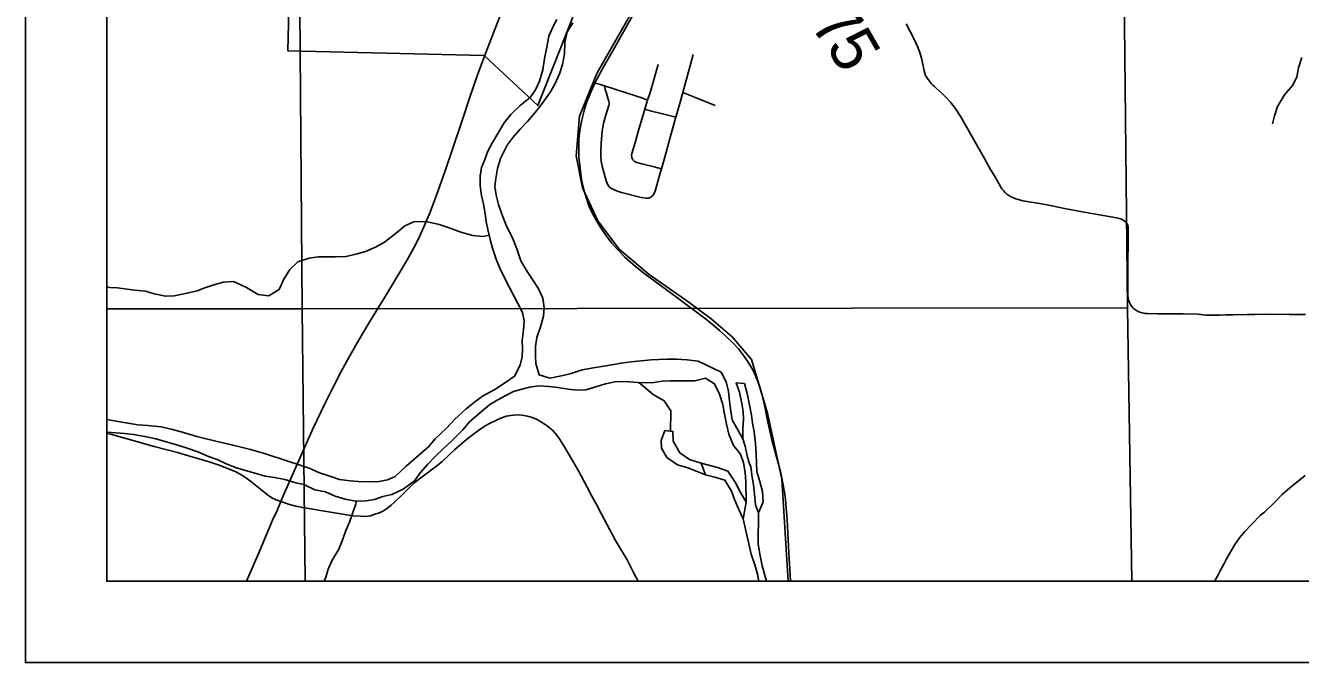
# Model space of a CAD drawing. Extents: x 0 to 34, y 0 to 22.
# Drawn here: x 1.76 to 3.328, y 14.287 to 15.071 of the extents above; entities that cross this region are included whole.
import ezdxf

# ---------------------------------------------------------------- set-up
doc = ezdxf.new("R2010")
doc.units = 0
for name, color, linetype in [('GM_X_County_Road', 7, 'Continuous'), ('GM_X_County_Road_Text', 7, 'Continuous'), ('GM_X_County_Text', 7, 'Continuous'), ('GM_X_Interchange_Ramps', 7, 'Continuous'), ('GM_X_State_Route', 7, 'Continuous'), ('GM_X_State_Shield', 7, 'Continuous'), ('GM_X_Township_Road', 7, 'Continuous'), ('GM_X_Township_Text', 7, 'Continuous'), ('SH_Data', 7, 'Continuous')]:
    doc.layers.add(name, color=color, linetype=linetype)

msp = doc.modelspace()

# ---------------------------------------------------------------- linework, layer by layer
at = {"layer": 'GM_X_County_Road'}
for points in [[(2.3247, 15.0329), (2.3399, 15.072), (2.3515, 15.1008), (2.3595, 15.1196), (2.3705, 15.1452), (2.3805, 15.168)], [(2.2971, 14.9535), (2.3072, 14.9837), (2.3156, 15.0085), (2.3222, 15.0263), (2.3247, 15.0329)], [(2.0742, 14.4847), (2.0773, 14.4916), (2.1142, 14.575), (2.1275, 14.6031), (2.1385, 14.6255), (2.1485, 14.6449), (2.1575, 14.6613), (2.1683, 14.6802), (2.1826, 14.7043), (2.1961, 14.7265), (2.1988, 14.7309), (2.2008, 14.7342), (2.2293, 14.7815), (2.2354, 14.7923), (2.2412, 14.8032), (2.2453, 14.8116), (2.2503, 14.8229), (2.258, 14.8409), (2.266, 14.8629), (2.2758, 14.8905), (2.2857, 14.9196), (2.2971, 14.9535)], [(1.8602, 14.5684), (1.8646, 14.5675), (1.8883, 14.5612), (1.9185, 14.5526), (1.9471, 14.5449), (1.9606, 14.541)], [(1.9606, 14.541), (1.9722, 14.5376), (1.9862, 14.5334), (1.9986, 14.5294), (2.0098, 14.5251), (2.0188, 14.5211), (2.0242, 14.5182), (2.0294, 14.515), (2.0369, 14.5096), (2.0492, 14.5001), (2.0579, 14.4929), (2.0632, 14.4893), (2.0685, 14.4869), (2.0742, 14.4847)], [(2.0321, 14.3866), (2.0485, 14.4246), (2.0642, 14.4618), (2.0696, 14.4738), (2.0742, 14.4847)]]:
    msp.add_lwpolyline(points, dxfattribs=at)
at = {"layer": 'GM_X_County_Road_Text'}
for points in [[(3.3297, 15.0312), (3.3257, 15.0182), (3.3239, 15.0072), (3.319, 14.9969), (3.3085, 14.985), (3.2999, 14.9709), (3.2962, 14.9595), (3.294, 14.9496)], [(2.3306, 14.8123), (2.3231, 14.811), (2.3102, 14.8121), (2.2958, 14.8163), (2.2814, 14.8216), (2.2689, 14.8257), (2.2526, 14.8295), (2.2378, 14.8287), (2.2268, 14.8238), (2.2166, 14.8154), (2.2018, 14.804), (2.1905, 14.7976), (2.1783, 14.7922), (2.1681, 14.7896), (2.1545, 14.7861), (2.1412, 14.7857), (2.1207, 14.7857), (2.109, 14.7842), (2.095, 14.7796), (2.0855, 14.7701), (2.0779, 14.7584), (2.0722, 14.7458), (2.0597, 14.7379), (2.0465, 14.7394), (2.0321, 14.7481), (2.0161, 14.7556), (2.0036, 14.7545), (1.9919, 14.7514), (1.9809, 14.7476), (1.9714, 14.7438), (1.957, 14.7407), (1.943, 14.7377), (1.9324, 14.7373), (1.9183, 14.7403), (1.9077, 14.7437), (1.8948, 14.7448), (1.8854, 14.746), (1.8732, 14.7475), (1.8638, 14.7482), (1.8602, 14.7488)], [(2.5144, 14.6312), (2.5189, 14.6274), (2.5322, 14.6164), (2.5455, 14.6085), (2.5538, 14.5964), (2.5534, 14.5713)], [(2.591, 14.532), (2.577, 14.5365), (2.5649, 14.5448), (2.5569, 14.5589), (2.5565, 14.571), (2.5463, 14.5721), (2.5421, 14.56), (2.5425, 14.5505), (2.549, 14.5391), (2.5619, 14.5297), (2.5747, 14.5263), (2.5861, 14.5217), (2.5967, 14.5176)], [(2.1673, 14.4852), (2.1665, 14.4817), (2.162, 14.4688), (2.1586, 14.4593), (2.1541, 14.4491), (2.1503, 14.4385), (2.1457, 14.4263), (2.1374, 14.4127), (2.1325, 14.4017), (2.1295, 14.3918), (2.1274, 14.3866)]]:
    msp.add_lwpolyline(points, dxfattribs=at)
at = {"layer": 'GM_X_County_Text'}
msp.add_lwpolyline([(2.5564, 15.1755), (2.4633, 15.0123), (2.4414, 14.9588), (2.4376, 14.91), (2.4453, 14.8709), (2.4642, 14.8303), (2.4905, 14.7953), (2.5272, 14.7641), (2.5746, 14.7309), (2.6035, 14.7095), (2.6294, 14.6873), (2.6532, 14.6593), (2.6729, 14.5935), (2.6905, 14.5124), (2.6983, 14.3866)], dxfattribs=at)
at = {"layer": 'GM_X_Interchange_Ramps'}
msp.add_line((2.5219, 14.9677), (2.5253, 14.9785), dxfattribs=at)
for points in [[(2.8432, 15.0726), (2.8531, 15.0536), (2.8572, 15.0448), (2.86, 15.0374), (2.862, 15.0302), (2.864, 15.0209), (2.8654, 15.0149), (2.8663, 15.0117), (2.8672, 15.0091), (2.8687, 15.0065), (2.8705, 15.0041), (2.8722, 15.0015), (2.8741, 14.9992), (2.8761, 14.9972), (2.8781, 14.9954), (2.8803, 14.9935), (2.8871, 14.9873), (2.8915, 14.9828), (2.8979, 14.976), (2.9036, 14.9688), (2.9104, 14.9582), (2.9229, 14.9365), (2.938, 14.9095), (2.9472, 14.8933), (2.9518, 14.8854), (2.9594, 14.8722), (2.961, 14.8697), (2.9629, 14.8673), (2.9649, 14.865), (2.9672, 14.863), (2.9697, 14.8612), (2.9725, 14.8596), (2.9781, 14.8572), (2.9868, 14.8549), (3.0025, 14.8522), (3.0165, 14.8497), (3.038, 14.8452), (3.0622, 14.8408), (3.081, 14.8375), (3.102, 14.8337), (3.1052, 14.8329), (3.108, 14.832), (3.1108, 14.8307), (3.1135, 14.8283), (3.1154, 14.8255), (3.1162, 14.8228), (3.1164, 14.8195), (3.1165, 14.8132), (3.1162, 14.8007), (3.1161, 14.7821), (3.1161, 14.7634), (3.1159, 14.7448), (3.1161, 14.7386), (3.1164, 14.7355), (3.1169, 14.7325), (3.1178, 14.7297), (3.1191, 14.727), (3.1209, 14.7246), (3.123, 14.7224), (3.1253, 14.7205), (3.1279, 14.719), (3.1307, 14.7177), (3.1336, 14.7168), (3.137, 14.7162), (3.1402, 14.716), (3.153, 14.7157), (3.1839, 14.7156), (3.2022, 14.7151), (3.212, 14.7142), (3.2213, 14.7142), (3.2295, 14.7142), (3.2365, 14.7145), (3.2456, 14.7146), (3.2627, 14.7147), (3.2722, 14.715), (3.2915, 14.7151), (3.3148, 14.7149), (3.3344, 14.7149)], [(2.5253, 14.9785), (2.5287, 14.9892), (2.5383, 15.0223)], [(2.5814, 15.0347), (2.5798, 15.0287), (2.5707, 14.9956), (2.5687, 14.9882)], [(2.4606, 14.9996), (2.4659, 14.9981), (2.4724, 14.9961)], [(2.5422, 14.8943), (2.5412, 14.8906), (2.538, 14.8786), (2.5346, 14.8666), (2.5334, 14.8637), (2.5318, 14.8611), (2.5294, 14.8591), (2.5265, 14.858), (2.5235, 14.8579), (2.5174, 14.859), (2.4932, 14.865), (2.4872, 14.8669), (2.4844, 14.8681), (2.4816, 14.8695), (2.479, 14.8712), (2.4769, 14.8735), (2.4755, 14.8763), (2.4745, 14.8792), (2.4696, 14.8973), (2.4684, 14.9034), (2.4678, 14.9096), (2.4677, 14.9158), (2.4683, 14.9252), (2.4696, 14.9407), (2.4711, 14.9499), (2.4734, 14.959), (2.4774, 14.9708), (2.4778, 14.9721), (2.478, 14.9738), (2.4779, 14.9754), (2.4777, 14.9769), (2.4768, 14.9799), (2.4755, 14.9841), (2.4743, 14.9883), (2.4733, 14.9918), (2.4724, 14.9961)], [(2.4724, 14.9961), (2.5103, 14.9839), (2.5184, 14.9815), (2.5211, 14.9803), (2.5253, 14.9785)], [(2.5687, 14.9882), (2.5648, 14.9746), (2.5601, 14.9578)], [(2.5687, 14.9882), (2.5872, 14.9807), (2.6085, 14.972)], [(2.5422, 14.8943), (2.5363, 14.8958), (2.5333, 14.8965), (2.5181, 14.9001), (2.5121, 14.9018), (2.5093, 14.9032), (2.507, 14.9053), (2.5058, 14.9081), (2.5057, 14.9112), (2.5064, 14.9143), (2.511, 14.9292), (2.5142, 14.9413), (2.5193, 14.9594), (2.5219, 14.9677)], [(2.5219, 14.9677), (2.5271, 14.9661), (2.53, 14.9652), (2.5418, 14.9622), (2.5536, 14.9593), (2.5601, 14.9578)], [(2.5601, 14.9578), (2.5597, 14.9566), (2.5546, 14.9387), (2.5455, 14.9056), (2.5422, 14.8943)], [(2.5136, 14.3866), (2.5082, 14.3966), (2.5001, 14.4129), (2.4859, 14.4369), (2.468, 14.4699), (2.4626, 14.4809), (2.4568, 14.4914), (2.4508, 14.5024), (2.4406, 14.5216), (2.4331, 14.5353), (2.4222, 14.5532), (2.4172, 14.5612), (2.4135, 14.5665), (2.4083, 14.5724), (2.4042, 14.5758), (2.4019, 14.5778), (2.3994, 14.5796), (2.3941, 14.583), (2.3887, 14.5861), (2.3835, 14.5881), (2.3776, 14.5896), (2.3706, 14.5909), (2.3638, 14.5913), (2.3571, 14.5906), (2.3512, 14.5896), (2.3448, 14.5875), (2.3394, 14.5849), (2.3315, 14.5813), (2.3254, 14.578), (2.3178, 14.5726), (2.3111, 14.5675), (2.3024, 14.561), (2.2884, 14.5489), (2.2725, 14.5339), (2.2677, 14.5299), (2.2479, 14.515), (2.2379, 14.5072), (2.2314, 14.5007), (2.2242, 14.4938)], [(3.2223, 14.3866), (3.2227, 14.3872), (3.2269, 14.3945), (3.2296, 14.3993), (3.2318, 14.4038), (3.2342, 14.4086), (3.2372, 14.4141), (3.2413, 14.4213), (3.2473, 14.4317), (3.2531, 14.4401), (3.2597, 14.4479), (3.2679, 14.4563), (3.2792, 14.4678), (3.2839, 14.4718), (3.295, 14.4824), (3.3059, 14.4933), (3.3151, 14.5014), (3.3339, 14.5169)], [(2.2242, 14.4938), (2.2141, 14.484), (2.2098, 14.4801), (2.2042, 14.4759), (2.2016, 14.4742), (2.199, 14.4726), (2.1943, 14.4706), (2.1912, 14.4694), (2.1879, 14.4682), (2.1847, 14.4673), (2.1818, 14.4668), (2.1783, 14.4665), (2.1722, 14.4666), (2.1629, 14.4673), (2.1353, 14.4718), (2.1013, 14.4773), (2.0928, 14.479), (2.0851, 14.4811), (2.0742, 14.4847)]]:
    msp.add_lwpolyline(points, dxfattribs=at)
at = {"layer": 'GM_X_State_Route'}
for points in [[(4.1201, 16.507), (4.1149, 16.7255), (3.8667, 16.7261), (3.8624, 16.726), (3.8538, 16.7259), (3.7775, 16.7251), (3.6944, 16.7259), (3.6091, 16.7254), (3.5492, 16.7252), (3.5064, 16.7242), (3.4642, 16.7247), (3.3781, 16.7258), (3.3363, 16.7271), (3.2929, 16.7282), (3.2508, 16.7281), (3.0563, 16.7255), (2.994, 16.7266), (1.8602, 16.7212), (1.8602, 14.3866), (4.1451, 14.3866)], [(2.087, 15.2089), (2.0829, 15.0394), (2.3245, 15.0335), (2.3902, 14.972), (2.4333, 15.0808)]]:
    msp.add_lwpolyline(points, dxfattribs=at)
for points in [[(2.0927, 15.7254), (3.1048, 15.7312), (3.1155, 14.7229), (2.1005, 14.722)], [(1.8602, 15.723), (1.8602, 14.7217), (2.1005, 14.722), (2.0927, 15.7254)], [(1.8602, 14.7217), (1.8602, 14.3866), (2.104, 14.3866), (2.1005, 14.722)], [(2.104, 14.3866), (3.121, 14.3866), (3.1155, 14.7229), (2.1005, 14.722)]]:
    msp.add_lwpolyline(points, close=True, dxfattribs=at)
at = {"layer": 'GM_X_State_Shield'}
msp.add_line((2.591, 14.532), (2.5967, 14.5176), dxfattribs=at)
for points in [[(2.4138, 15.0777), (2.4085, 15.0678), (2.404, 15.0572), (2.4013, 15.0439), (2.3987, 15.0299), (2.3964, 15.0159), (2.3923, 15.0018), (2.3874, 14.9912), (2.3809, 14.9817), (2.3684, 14.9719), (2.3571, 14.9608), (2.3491, 14.9506), (2.3412, 14.9377), (2.3347, 14.9267), (2.3287, 14.9157), (2.3253, 14.9054), (2.3211, 14.8956), (2.3196, 14.885), (2.3196, 14.8732), (2.3212, 14.8615), (2.3235, 14.8508), (2.3257, 14.8387), (2.3269, 14.8292), (2.3288, 14.8194), (2.3318, 14.8072), (2.3345, 14.7963), (2.3391, 14.783), (2.3436, 14.772), (2.3497, 14.7591), (2.3657, 14.7284), (2.3714, 14.7174), (2.3736, 14.7072), (2.3725, 14.6958), (2.371, 14.6829), (2.3714, 14.6727), (2.371, 14.6629), (2.3684, 14.6526), (2.3616, 14.639), (2.3506, 14.6314), (2.3373, 14.6226), (2.3222, 14.6143), (2.3123, 14.607), (2.3021, 14.5987), (2.2877, 14.5858), (2.2779, 14.5748), (2.2639, 14.5618), (2.2563, 14.5524), (2.2283, 14.5281), (2.215, 14.5155), (2.2055, 14.5113), (2.1953, 14.5094), (2.1828, 14.509), (2.1695, 14.5094), (2.1597, 14.5101), (2.1464, 14.512), (2.1331, 14.5165), (2.1218, 14.5199), (2.1089, 14.5256), (2.0979, 14.5294), (2.0827, 14.5343), (2.0543, 14.5437), (2.0368, 14.5486), (2.0205, 14.5528), (2.0084, 14.5558), (1.9925, 14.5596), (1.9807, 14.5622), (1.9708, 14.5648), (1.9545, 14.5697), (1.9394, 14.5739), (1.9272, 14.5765), (1.9106, 14.5784), (1.8984, 14.5791), (1.881, 14.5818), (1.8673, 14.5844), (1.8602, 14.5856)], [(2.5875, 14.6575), (2.5738, 14.659), (2.561, 14.6601), (2.5492, 14.6601), (2.5393, 14.6597), (2.5295, 14.6589), (2.5052, 14.6566), (2.4927, 14.6551), (2.4814, 14.6531), (2.4689, 14.6509), (2.4586, 14.6493), (2.445, 14.6467), (2.4313, 14.6421), (2.4196, 14.6394), (2.4052, 14.6367), (2.3919, 14.6405), (2.3877, 14.6545), (2.3873, 14.6644), (2.3873, 14.6754), (2.3892, 14.6864), (2.3934, 14.6997), (2.3971, 14.7129), (2.3983, 14.7232), (2.3964, 14.7349), (2.3907, 14.7474), (2.3838, 14.758), (2.377, 14.7679), (2.3694, 14.7808), (2.3645, 14.7955), (2.3591, 14.8092), (2.3519, 14.8236), (2.3455, 14.8395), (2.342, 14.8501), (2.339, 14.8619), (2.3375, 14.8725), (2.3386, 14.8823), (2.3408, 14.8945), (2.3446, 14.907), (2.3526, 14.9233), (2.3598, 14.9332), (2.3685, 14.943), (2.3776, 14.9525), (2.387, 14.9635), (2.3946, 14.973), (2.4059, 14.989), (2.4116, 14.9992), (2.4169, 15.011), (2.4207, 15.0227), (2.423, 15.0356), (2.4237, 15.05), (2.4263, 15.0625), (2.4332, 15.0736)], [(2.6424, 14.5618), (2.6295, 14.5853), (2.6275, 14.5959), (2.6259, 14.6084), (2.6247, 14.6202), (2.6219, 14.6319), (2.6157, 14.644), (2.5875, 14.6575)], [(1.8602, 14.57), (1.8715, 14.5693), (1.8821, 14.5685), (1.8931, 14.5674), (1.9072, 14.5648), (1.9204, 14.5617), (1.936, 14.5572), (1.9489, 14.5538), (1.9591, 14.5504), (1.972, 14.5459), (1.9853, 14.5402), (1.9959, 14.5364), (2.0061, 14.5315), (2.0183, 14.5266), (2.0308, 14.5228), (2.0441, 14.5191), (2.055, 14.5161), (2.0664, 14.5142), (2.0793, 14.5119), (2.0926, 14.5078), (2.1024, 14.5055), (2.1161, 14.4991), (2.129, 14.4968), (2.1411, 14.4912), (2.1533, 14.4878), (2.1661, 14.4851), (2.179, 14.4855), (2.1893, 14.4874), (2.1999, 14.4909), (2.2109, 14.4935), (2.2245, 14.5), (2.2385, 14.5102), (2.2461, 14.5205), (2.2552, 14.5307), (2.2643, 14.5406), (2.2745, 14.5501), (2.2843, 14.5588), (2.298, 14.5729), (2.3063, 14.5828), (2.318, 14.593), (2.3313, 14.604), (2.3411, 14.6097), (2.351, 14.6151), (2.3605, 14.62), (2.3707, 14.623), (2.3802, 14.6253), (2.3919, 14.6269), (2.4041, 14.6261), (2.4151, 14.625), (2.4276, 14.6231), (2.4393, 14.6216), (2.4495, 14.622), (2.4628, 14.6262), (2.4734, 14.6296), (2.4852, 14.6319), (2.4977, 14.6323), (2.5132, 14.6312), (2.5235, 14.6308), (2.5329, 14.6312), (2.5432, 14.6328), (2.553, 14.6332), (2.5833, 14.6332), (2.5966, 14.6366)], [(2.5966, 14.6366), (2.6075, 14.6295), (2.6137, 14.617), (2.618, 14.6042), (2.62, 14.5924), (2.6224, 14.5799), (2.6251, 14.5678), (2.6309, 14.5538), (2.6394, 14.5429), (2.6433, 14.5323), (2.6451, 14.5205), (2.6462, 14.5093), (2.6467, 14.4838)], [(2.6617, 14.4707), (2.6676, 14.4844), (2.6667, 14.4969), (2.6632, 14.5094), (2.6597, 14.5215), (2.6592, 14.5317), (2.6587, 14.5435), (2.6582, 14.5567), (2.6562, 14.5704), (2.6542, 14.581), (2.653, 14.5912), (2.6506, 14.6037), (2.6478, 14.6177), (2.6443, 14.6298), (2.6344, 14.6309), (2.6383, 14.6192), (2.6411, 14.6055), (2.6427, 14.5957), (2.6432, 14.5862), (2.6425, 14.5741), (2.6424, 14.5618)], [(2.6424, 14.5618), (2.6451, 14.5529), (2.6478, 14.5409), (2.6497, 14.5336), (2.6524, 14.5274), (2.6539, 14.5147), (2.6555, 14.5051), (2.6566, 14.4939), (2.6578, 14.4807), (2.6617, 14.4707)], [(2.6467, 14.4838), (2.639, 14.4966), (2.6329, 14.5087), (2.624, 14.5219), (2.6111, 14.5267), (2.591, 14.532)], [(2.5967, 14.5176), (2.6078, 14.5149), (2.6203, 14.5109), (2.6284, 14.4973), (2.6323, 14.4871), (2.6373, 14.4757), (2.6428, 14.4636)], [(2.6428, 14.4636), (2.6467, 14.4838)], [(2.6428, 14.4636), (2.6526, 14.4201), (2.6573, 14.4069), (2.6604, 14.3955), (2.6623, 14.3866)], [(2.6716, 14.3866), (2.6699, 14.3926), (2.6664, 14.4054), (2.6632, 14.4198), (2.6612, 14.4327), (2.6617, 14.4707)]]:
    msp.add_lwpolyline(points, dxfattribs=at)
at = {"layer": 'GM_X_Township_Road'}
for points in [[(2.4606, 14.9996), (2.4708, 15.0187), (2.4844, 15.0431), (2.5014, 15.0728), (2.5122, 15.0918), (2.5385, 15.1377), (2.5601, 15.1753), (2.5691, 15.1916), (2.5803, 15.2097), (2.5893, 15.223), (2.5969, 15.2329), (2.6066, 15.2452), (2.6166, 15.2568), (2.6377, 15.2802), (2.6483, 15.2911)], [(2.7012, 14.3866), (2.7007, 14.3941), (2.699, 14.4217), (2.6969, 14.4627), (2.6959, 14.4771), (2.6945, 14.4912), (2.6919, 14.5054), (2.689, 14.5201), (2.6837, 14.5396), (2.6782, 14.5606), (2.6724, 14.5865), (2.6689, 14.6037), (2.664, 14.6228), (2.6608, 14.6325), (2.6568, 14.6421), (2.6535, 14.649), (2.6483, 14.6575), (2.6426, 14.6655), (2.637, 14.6726), (2.6304, 14.6797), (2.622, 14.6877), (2.6137, 14.6953), (2.6076, 14.7005), (2.598, 14.7082), (2.5608, 14.736), (2.5222, 14.7645), (2.5103, 14.7741), (2.4974, 14.7856), (2.4882, 14.795), (2.4815, 14.8026), (2.4747, 14.8111), (2.4677, 14.8216), (2.4631, 14.8291), (2.4575, 14.8391), (2.4536, 14.8477), (2.4505, 14.8564), (2.4476, 14.8656), (2.4458, 14.873), (2.4441, 14.8814), (2.4427, 14.8907), (2.4418, 14.8988), (2.4412, 14.9047), (2.4409, 14.9075), (2.4408, 14.9105), (2.4406, 14.9157), (2.4406, 14.9257), (2.4408, 14.9313), (2.4418, 14.9408), (2.4435, 14.9505), (2.4455, 14.9594), (2.4477, 14.9674), (2.4506, 14.9766), (2.4553, 14.9883), (2.4606, 14.9996)]]:
    msp.add_lwpolyline(points, dxfattribs=at)
at = {"layer": 'SH_Data'}
for points in [[(1.7602, 21.2866), (8.7602, 21.2866), (8.7602, 14.2866), (1.7602, 14.2866)], [(1.8602, 21.1866), (8.6602, 21.1866), (8.6602, 14.3866), (1.8602, 14.3866)]]:
    msp.add_lwpolyline(points, close=True, dxfattribs=at)

# ---------------------------------------------------------------- texts
at = {"layer": 'GM_X_Township_Text'}
for s, rotation, p in [('7', 309.6343, (2.7233, 15.0703)), ('5', 299.874, (2.7441, 15.0455))]:
    msp.add_text(s, height=0.0568, rotation=rotation, dxfattribs=at).set_placement(p)

doc.saveas('drawing.dxf')
